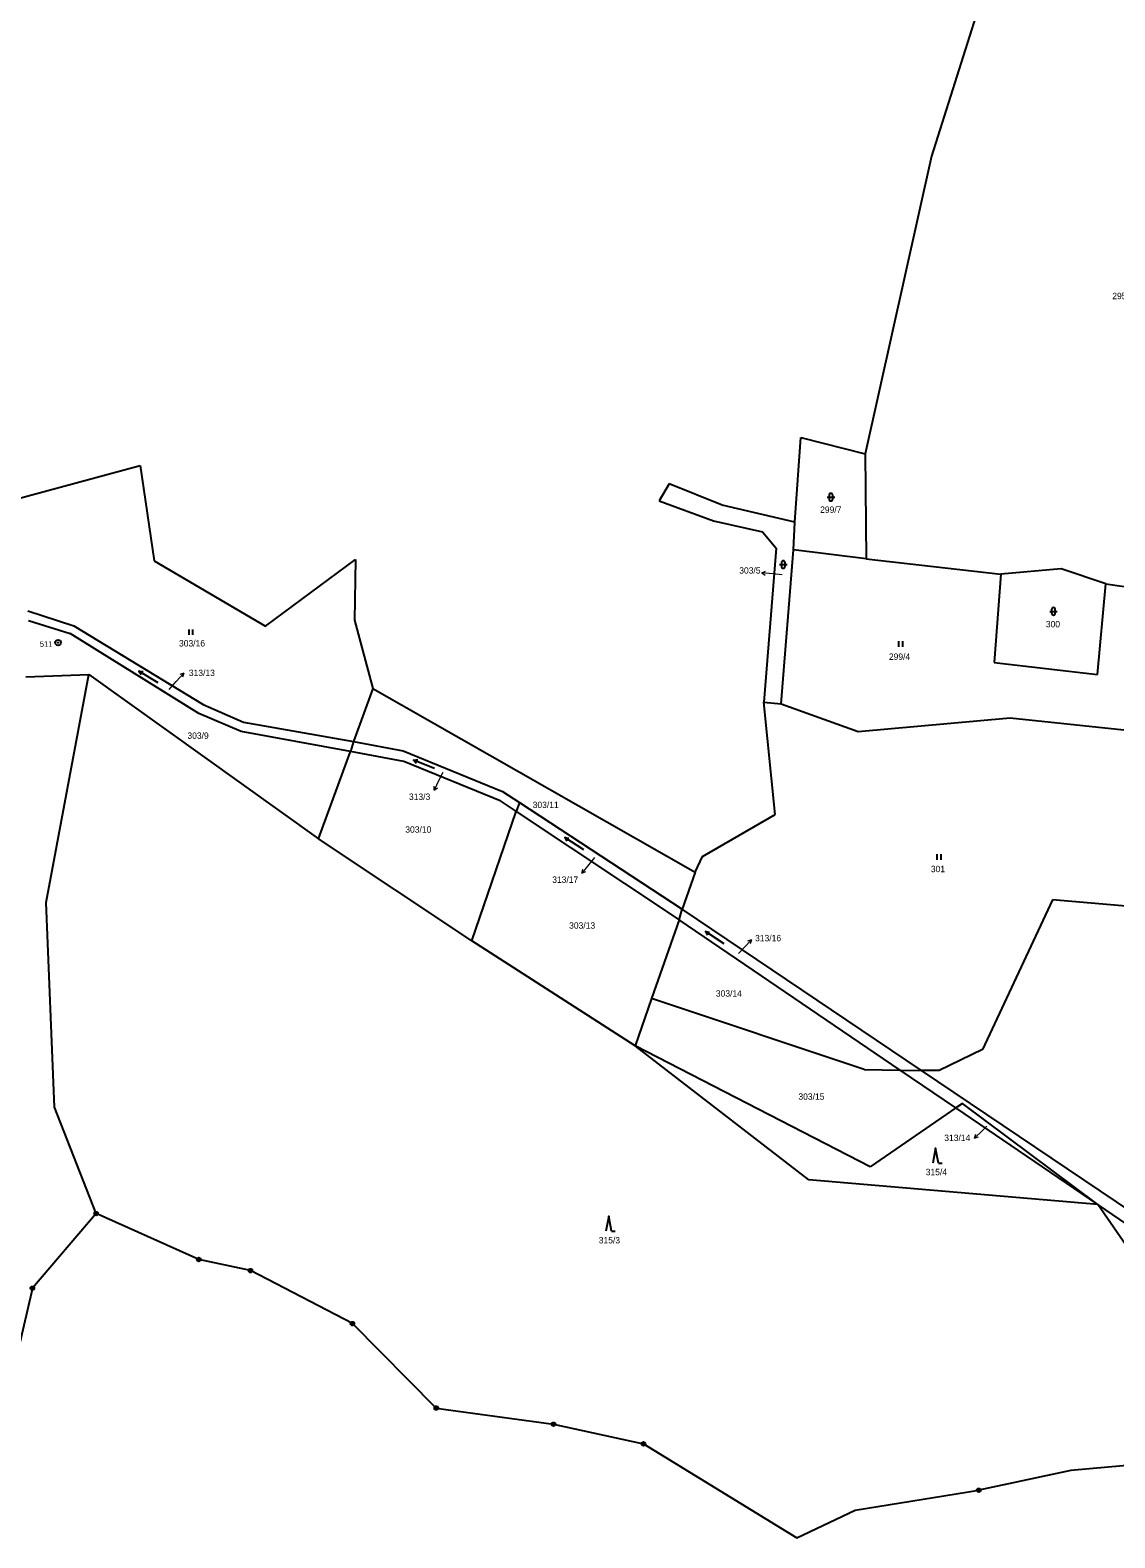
# Model space of a CAD drawing. Extents: x -765428 to -762163, y -1107632 to -1104975.
# Drawn here: x -763558.6 to -763268.9, y -1107263.7 to -1106861.1 of the extents above; entities that cross this region are included whole.
import ezdxf
from ezdxf.enums import TextEntityAlignment as Align

# ---------------------------------------------------------------- set-up
doc = ezdxf.new("R2010")
doc.units = 0
doc.header["$LTSCALE"] = 0.68
for name, color, linetype, lineweight in [('1', 7, 'Continuous', 25), ('3', 7, 'Continuous', 25), ('7', 7, 'Continuous', 13), ('8', 7, 'Continuous', 25)]:
    doc.layers.add(name, color=color, linetype=linetype, lineweight=lineweight)
doc.layers.add('2', color=7, linetype='Continuous')

msp = doc.modelspace()

# ---------------------------------------------------------------- linework, layer by layer
at = {"layer": '1'}
for p, q in [((-763301.28, -1106842.27), (-763317.91, -1106894.73)), ((-763317.91, -1106894.73), (-763335.61, -1106974.22)), ((-763354.4, -1106992.52), (-763352.77, -1106969.89)), ((-763352.77, -1106969.89), (-763335.61, -1106974.22)), ((-763335.61, -1106974.22), (-763335.32, -1107002.31)), ((-763569.14, -1106988.14), (-763529.25, -1106977.37)), ((-763529.25, -1106977.37), (-763525.54, -1107002.82)), ((-763387.96, -1106982.28), (-763390.59, -1106986.77)), ((-763373.78, -1106987.93), (-763387.96, -1106982.28)), ((-763390.59, -1106986.77), (-763376.08, -1106992.16)), ((-763354.4, -1106992.52), (-763373.78, -1106987.93)), ((-763376.08, -1106992.16), (-763362.99, -1106995.09)), ((-763354.74, -1106999.85), (-763354.4, -1106992.52)), ((-763362.99, -1106995.09), (-763359.36, -1106999.39)), ((-763359.36, -1106999.39), (-763362.66, -1107040.57)), ((-763358.02, -1107041.03), (-763354.74, -1106999.85)), ((-763335.32, -1107002.31), (-763354.74, -1106999.85)), ((-763525.54, -1107002.82), (-763495.81, -1107020.28)), ((-763495.81, -1107020.28), (-763471.77, -1107002.48)), ((-763471.77, -1107002.48), (-763471.99, -1107018.7)), ((-763335.32, -1107002.31), (-763299.32, -1107006.4)), ((-763283.28, -1107004.98), (-763299.32, -1107006.4)), ((-763271.34, -1107008.99), (-763283.28, -1107004.98)), ((-763299.32, -1107006.4), (-763301.1, -1107029.93)), ((-763273.57, -1107033.14), (-763271.34, -1107008.99)), ((-763271.34, -1107008.99), (-763230.27, -1107014.96)), ((-763559.24, -1107016.19), (-763546.96, -1107020.15)), ((-763559.08, -1107018.71), (-763547.96, -1107022.21)), ((-763546.96, -1107020.15), (-763512.42, -1107041.22)), ((-763471.99, -1107018.7), (-763467.12, -1107036.9)), ((-763513.57, -1107043.62), (-763547.96, -1107022.21)), ((-763559.82, -1107033.81), (-763542.93, -1107033.17)), ((-763554.34, -1107094.04), (-763542.93, -1107033.17)), ((-763542.93, -1107033.17), (-763481.65, -1107077.08)), ((-763301.1, -1107029.93), (-763273.57, -1107033.14)), ((-763467.12, -1107036.9), (-763472.23, -1107051.08)), ((-763467.12, -1107036.9), (-763381, -1107085.91)), ((-763512.42, -1107041.22), (-763501.66, -1107045.92)), ((-763362.66, -1107040.57), (-763358.02, -1107041.03)), ((-763359.63, -1107070.55), (-763362.66, -1107040.57)), ((-763358.02, -1107041.03), (-763337.5, -1107048.39)), ((-763502.28, -1107048.43), (-763513.57, -1107043.62)), ((-763337.5, -1107048.39), (-763296.9, -1107044.7)), ((-763296.9, -1107044.7), (-763253.19, -1107049.31)), ((-763473.05, -1107053.74), (-763502.28, -1107048.43)), ((-763501.66, -1107045.92), (-763472.23, -1107051.08)), ((-763472.23, -1107051.08), (-763473.05, -1107053.74)), ((-763472.23, -1107051.08), (-763458.99, -1107053.55)), ((-763458.99, -1107053.55), (-763432.46, -1107064.42)), ((-763481.65, -1107077.08), (-763473.05, -1107053.74)), ((-763458.78, -1107056.38), (-763473.05, -1107053.74)), ((-763433.08, -1107066.93), (-763458.78, -1107056.38)), ((-763432.46, -1107064.42), (-763427.91, -1107067.37)), ((-763433.08, -1107066.93), (-763428.82, -1107069.79)), ((-763427.91, -1107067.37), (-763384.46, -1107095.84)), ((-763440.68, -1107104.28), (-763428.82, -1107069.79)), ((-763379.02, -1107081.8), (-763359.63, -1107070.55)), ((-763440.68, -1107104.28), (-763481.65, -1107077.08)), ((-763381, -1107085.91), (-763379.02, -1107081.8)), ((-763381, -1107085.91), (-763384.46, -1107095.84)), ((-763285.6, -1107093.35), (-763304.26, -1107133.32)), ((-763257.58, -1107095.73), (-763285.6, -1107093.35)), ((-763552.14, -1107148.69), (-763554.34, -1107094.04)), ((-763385.28, -1107098.69), (-763384.46, -1107095.84)), ((-763320.55, -1107138.92), (-763384.46, -1107095.84)), ((-763385.28, -1107098.69), (-763392.63, -1107119.72)), ((-763326.23, -1107138.83), (-763385.28, -1107098.69)), ((-763397.04, -1107132.36), (-763440.68, -1107104.28)), ((-763392.63, -1107119.72), (-763397.04, -1107132.36)), ((-763335.88, -1107138.69), (-763392.63, -1107119.72)), ((-763350.61, -1107168.1), (-763397.04, -1107132.36)), ((-763334.25, -1107164.6), (-763397.04, -1107132.36)), ((-763304.26, -1107133.32), (-763315.79, -1107138.94)), ((-763335.88, -1107138.69), (-763326.23, -1107138.83)), ((-763326.23, -1107138.83), (-763320.55, -1107138.92)), ((-763311.41, -1107148.91), (-763326.23, -1107138.83)), ((-763315.79, -1107138.94), (-763320.55, -1107138.92)), ((-763211.14, -1107212.68), (-763320.55, -1107138.92)), ((-763541.02, -1107177.13), (-763552.14, -1107148.69)), ((-763311.41, -1107148.91), (-763334.25, -1107164.6)), ((-763309.6, -1107147.75), (-763311.41, -1107148.91)), ((-763273.48, -1107174.7), (-763311.41, -1107148.91)), ((-763273.48, -1107174.7), (-763309.6, -1107147.75)), ((-763273.48, -1107174.7), (-763350.61, -1107168.1)), ((-763541.02, -1107177.13), (-763558.04, -1107197.06)), ((-763513.59, -1107189.38), (-763541.02, -1107177.13)), ((-763212.4, -1107216.23), (-763273.48, -1107174.7)), ((-763235.46, -1107229.82), (-763273.48, -1107174.7)), ((-763499.76, -1107192.36), (-763513.59, -1107189.38)), ((-763472.54, -1107206.52), (-763499.76, -1107192.36)), ((-763558.04, -1107197.06), (-763564.57, -1107225.4)), ((-763450.15, -1107229.05), (-763472.54, -1107206.52)), ((-763450.15, -1107229.05), (-763418.84, -1107233.39)), ((-763418.84, -1107233.39), (-763394.8, -1107238.61)), ((-763394.8, -1107238.61), (-763353.86, -1107263.72)), ((-763280.67, -1107245.71), (-763305.27, -1107251.01)), ((-763261.71, -1107244.07), (-763280.67, -1107245.71)), ((-763338.25, -1107256.36), (-763305.27, -1107251.01)), ((-763353.86, -1107263.72), (-763338.25, -1107256.36))]:
    msp.add_line(p, q, dxfattribs=at)
msp.add_lwpolyline([(-763427.91, -1107067.37), (-763428.82, -1107069.79), (-763385.28, -1107098.69)], dxfattribs=at)
at = {"layer": '3'}
for p, q in [((-763345.741, -1106985.811), (-763343.739, -1106985.811)), ((-763345.241, -1106985.311), (-763345.241, -1106986.312)), ((-763344.239, -1106986.312), (-763344.239, -1106985.311)), ((-763358.471, -1107003.811), (-763356.469, -1107003.811)), ((-763357.971, -1107003.311), (-763357.971, -1107004.312)), ((-763356.969, -1107004.312), (-763356.969, -1107003.311)), ((-763286.311, -1107016.301), (-763284.309, -1107016.301)), ((-763285.811, -1107015.801), (-763285.811, -1107016.802)), ((-763284.809, -1107016.802), (-763284.809, -1107015.801)), ((-763516.191, -1107022.61), (-763516.191, -1107021.11)), ((-763515.19, -1107022.61), (-763515.19, -1107021.11)), ((-763326.561, -1107025.79), (-763326.561, -1107024.29)), ((-763325.56, -1107025.79), (-763325.56, -1107024.29)), ((-763529.562, -1107032.259), (-763528.466, -1107032.332)), ((-763456.204, -1107056.002), (-763455.11, -1107055.903)), ((-763415.816, -1107076.72), (-763414.723, -1107076.831)), ((-763316.321, -1107082.68), (-763316.321, -1107081.18)), ((-763315.32, -1107082.68), (-763315.32, -1107081.18)), ((-763378.266, -1107101.83), (-763377.173, -1107101.941)), ((-763316.04, -1107163.7), (-763315.044, -1107163.7)), ((-763403.34, -1107181.86), (-763402.344, -1107181.86))]:
    msp.add_line(p, q, dxfattribs=at)
for points in [[(-763524.419, -1107035.349), (-763529.562, -1107032.259), (-763528.982, -1107033.192)], [(-763450.641, -1107058.249), (-763456.204, -1107056.002), (-763455.486, -1107056.833)], [(-763410.784, -1107079.987), (-763415.816, -1107076.72), (-763415.269, -1107077.672)], [(-763373.234, -1107105.097), (-763378.266, -1107101.83), (-763377.719, -1107102.782)], [(-763316.04, -1107163.7), (-763316.79, -1107159.7), (-763317.54, -1107163.7)], [(-763403.34, -1107181.86), (-763404.09, -1107177.86), (-763404.84, -1107181.86)]]:
    msp.add_lwpolyline(points, dxfattribs=at)
for centre, start, end in [((-763344.74, -1106985.3109), 0, 180), ((-763344.74, -1106986.3109), 180, 359.98789), ((-763357.47, -1107003.3109), 0, 180), ((-763357.47, -1107004.3109), 180, 359.98789), ((-763285.31, -1107015.8009), 0, 180), ((-763285.31, -1107016.8009), 180, 359.98789)]:
    msp.add_arc(centre, 0.5, start, end, dxfattribs=at)
at = {"layer": '7'}
for p, q in [((-763363.22, -1107006.008), (-763362.266, -1107006.595)), ((-763517.602, -1107032.78), (-763518.644, -1107033.189)), ((-763450.746, -1107064.097), (-763449.856, -1107063.417)), ((-763411.238, -1107086.245), (-763410.226, -1107085.764)), ((-763365.983, -1107103.995), (-763367.033, -1107104.386)), ((-763306.435, -1107156.947), (-763305.361, -1107156.63))]:
    msp.add_line(p, q, dxfattribs=at)
for points in [[(-763357.74, -1107006.51), (-763360.23, -1107006.27), (-763363.22, -1107006.008), (-763362.178, -1107005.597)], [(-763521.54, -1107037.18), (-763519.61, -1107035.01), (-763517.602, -1107032.78), (-763517.9, -1107033.859)], [(-763448.43, -1107059.38), (-763449.43, -1107061.4), (-763450.746, -1107064.097), (-763450.757, -1107062.978)], [(-763407.93, -1107082.02), (-763409.39, -1107083.88), (-763411.238, -1107086.245), (-763411.016, -1107085.147)], [(-763369.43, -1107107.7), (-763368.03, -1107106.19), (-763365.983, -1107103.995), (-763366.3, -1107105.069)], [(-763303.07, -1107153.82), (-763304.24, -1107154.9), (-763306.435, -1107156.947), (-763306.044, -1107155.897)]]:
    msp.add_lwpolyline(points, dxfattribs=at)
at = {"layer": '8'}
for centre, radius in [((-763551.18, -1107024.6498), 0.75), ((-763551.18, -1107024.6498), 0.03), ((-763541.02, -1107177.1299), 0.5), ((-763541.02, -1107177.1299), 0.0303), ((-763513.59, -1107189.3799), 0.5), ((-763513.59, -1107189.3799), 0.0303), ((-763499.76, -1107192.3599), 0.5), ((-763499.76, -1107192.3599), 0.0303), ((-763558.04, -1107197.0599), 0.5), ((-763558.04, -1107197.0599), 0.0303), ((-763472.54, -1107206.5199), 0.5), ((-763472.54, -1107206.5199), 0.0303), ((-763450.15, -1107229.0499), 0.5), ((-763450.15, -1107229.0499), 0.0303), ((-763418.84, -1107233.3899), 0.5), ((-763418.84, -1107233.3899), 0.0303), ((-763394.8, -1107238.6099), 0.5), ((-763394.8, -1107238.6099), 0.0303), ((-763305.27, -1107251.0099), 0.5), ((-763305.27, -1107251.0099), 0.0303)]:
    msp.add_circle(centre, radius, dxfattribs=at)

# ---------------------------------------------------------------- texts
at = {"layer": '2'}
for s, p in [('295/3', (-763266.75, -1106932.935)), ('303/16', (-763515.39, -1107025.685)), ('303/10', (-763454.95, -1107075.395)), ('303/13', (-763411.19, -1107101.045)), ('303/14', (-763372, -1107119.185)), ('303/15', (-763349.95, -1107146.725)), ('315/4', (-763316.58, -1107166.875)), ('315/3', (-763403.91, -1107185.095))]:
    msp.add_text(s, height=1.7, dxfattribs=at).set_placement(p, align=Align.CENTER)
for s, p in [('299/7', (-763347.63, -1106989.995)), ('300', (-763287.34, -1107020.555)), ('299/4', (-763329.26, -1107029.255)), ('313/13', (-763516.24, -1107033.575)), ('303/9', (-763516.62, -1107050.345)), ('303/11', (-763424.4, -1107068.835)), ('301', (-763318.05, -1107085.955)), ('313/16', (-763365, -1107104.405))]:
    msp.add_text(s, height=1.7, dxfattribs=at).set_placement(p)
for s, p in [('303/5', (-763363.54, -1107006.215)), ('313/3', (-763451.76, -1107066.655)), ('313/17', (-763412.239, -1107088.805)), ('313/14', (-763307.519, -1107157.735))]:
    msp.add_text(s, height=1.7, dxfattribs=at).set_placement(p, align=Align.RIGHT)
at = {"layer": '8'}
msp.add_text('511', height=1.5, dxfattribs=at).set_placement((-763552.679, -1107025.767), align=Align.RIGHT)

doc.saveas('drawing.dxf')
